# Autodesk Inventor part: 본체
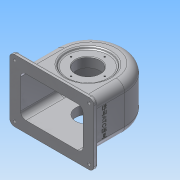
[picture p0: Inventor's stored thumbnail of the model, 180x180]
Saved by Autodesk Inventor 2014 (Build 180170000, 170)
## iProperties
Created: 2016-01
Part Number: 본체
Material: 알루미늄 6061
Document SubType Name: Modeling
Designer: user
Density: 2.71 g/cm^3
Appearance: 알루미늄 - 평지
Mass: 757.291 g
Surface Area: 1005.83 cm^2
Volume: 279.443 cm^3
Author: user
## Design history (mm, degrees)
sketch "스케치3"
  geometry: L1 (-57, -64)-(-57, 0); L2 (57, 0)-(57, -64); L3 (-57, -64)-(57, -64); A1 r 57 centre (0, 0) between (57, 0) and (-57, 0); 2 further points
  constraints: 6 end point, 3 point on circle, 2 tangent, 1 centre point, 1 coincident, 1 horizontal alignment, 1 parallel, 1 perpendicular, 1 vertical
  dimensions: "d6" = 64 distance of L1.start L1.end; "d7" = 121 vertical distance of L2.end point (0, 57)
extrude "돌출2" new body sketch "스케치3" distance "d8" = 77; taper "d9" = 0 deg
feature "쉘1" dims "d10" = 5
fillet "모깎기1" dims "d11" = 9
fillet "모깎기2" dims "d12" = 14
sketch "스케치4"
  geometry: L1 (100, 14)-(100, 63) reference; L2 (0, 77)-(86, 77) reference; L3 (-14, 14)-(-14, 63) reference; L4 (86, 0)-(0, 0) reference; L5 (-27, 90.5)-(113, 90.5); L6 (113, 90.5)-(113, -13.5); L7 (113, -13.5)-(-27, -13.5); L8 (-27, -13.5)-(-27, 90.5); A1 r 14 centre (86, 14) between (86, 0) and (100, 14) reference; A2 r 14 centre (86, 63) between (100, 63) and (86, 77) reference; A3 r 14 centre (0, 63) between (0, 77) and (-14, 63) reference; A4 r 14 centre (0, 14) between (-14, 14) and (0, 0) reference; 5 further points
  constraints: 8 end point, 4 midpoint, 2 parallel, 1 horizontal, 1 horizontal alignment, 1 perpendicular, 1 vertical alignment
  dimensions: "d13" = 104 distance of L7.end L5.start; "d14" = 140 distance of L5.start L5.end
extrude "돌출3" join sketch "스케치4" distance "d15" = 7; taper "d16" = 0 deg
sketch "스케치5"
  geometry: L1 (0, 63)-(0, 77) reference; L2 (0, 77)-(0, 77) reference; L3 (0, 63)-(0, 77) reference; L4 (0, 63)-(0, 63) reference; L5 (-57, 77)-(0, 77) reference; L6 (43, 72)-(0, 72) reference; L7 (35.747, 72)-(24, 58); L8 (24, 58)-(-4, 58); L9 (-4, 58)-(-4, 77); L10 (-64, -13.5)-(-64, 90.5) reference; L11 (0, 77)-(43, 77) reference; L12 (35.747, 72)-(-4, 72); 1 further point
  constraints: 8 end point, 2 parallel, 2 point on line, 1 horizontal alignment, 1 vertical
  dimensions: "d17" = 60 distance from line of L10 L9.end; "d18" = 50 deg angle of L8 L7; "d19" = 56 diameter of L7.end L9; "d20" = 19 distance between parallel lines of L8 L11
revolve "회전1" sketch "스케치5" stored, may be unused: angle "d21" = 90 deg
sketch "스케치6"
  geometry: L1 (0, 0)-(-57, 0) reference; L2 (-32, 58)-(24, 58) reference; L3 (43, 0)-(0, 0) reference; L4 (-4, -10)-(-4, 5); L5 (-64, -13.5)-(-64, 90.5) reference; L6 (-64, 5)-(0, 5) reference; L7 (-4, -10)-(27, -10); L8 (27, -10)-(27, 5); L9 (27, 5)-(-4, 5); 1 further point
  constraints: 8 end point, 2 parallel, 2 perpendicular, 1 horizontal alignment, 1 midpoint
  dimensions: "d69" = 60 distance between parallel lines of L5 L4; "d70" = 10 vertical distance of L3.start L4.start; "d71" = 62 diameter of L7.end L4
node "작업 평면2"
  node "작업 평면1"
sketch "스케치7"
  geometry: L1 (43, 0)-(-43, 0) reference; L2 (-57, 14)-(-57, 63) reference; C1 r 6 at (0, 38.5); 2 further points
  constraints: 1 centre point, 1 horizontal alignment, 1 midpoint, 1 vertical alignment
  dimensions: "d29" = 12 diameter of C1
extrude "돌출4" join sketch "스케치7" stored distance "d30" = 7; taper "d31" = 0 deg
fillet "모깎기3" dims "d32" = 3
hole "구멍1" diameter "d35" = 4.459; stored, may be unused: countersink angle "d39" = 90 deg, drill point angle "d41" = 0 deg; dims "d33" = 10, "d34" = 10, "d36" = 20, "d37" = 4, "d38" = 2, "d40" = 8
fillet "모깎기5" dims "d43" = 1
fillet "모깎기6" dims "d44" = 8
fillet "모깎기7" dims "d45" = 3
sketch "스케치9"
  geometry: C1 r 2.5 at (-19, -82.5); A1 r 5 centre (-19, -82.5) between (-24, -82.5) and (-19, -87.5) reference; 1 further point
  constraints: 1 centre point, 1 coincident
  dimensions: "d59" = 5 diameter of C1
extrude "돌출5" cut sketch "스케치9" stored distance "d60" = 7; taper "d61" = 0 deg
sketch "스케치10"
  geometry: C1 r 2.5 at (-19, 5.5); C2 r 2.5 at (105, 5.5); C3 r 2.5 at (105, -82.5); A1 r 5 centre (105, -82.5) between (105, -87.5) and (110, -82.5) reference; A2 r 5 centre (105, 5.5) between (110, 5.5) and (105, 10.5) reference; A3 r 5 centre (-19, 5.5) between (-19, 10.5) and (-24, 5.5) reference; 1 further point
  constraints: 3 centre point, 3 coincident, 2 equal radius
  dimensions: "d62" = 5 diameter of C1
extrude "돌출6" cut sketch "스케치10" stored distance "d63" = 7; taper "d64" = 0 deg
revolve "회전4" stored, may be unused: angle "d72" = 90 deg
hole "구멍3" diameter "d75" = 40; stored, may be unused: countersink angle "d79" = 90 deg, drill point angle "d81" = 0 deg; dims "d73" = 10, "d74" = 10, "d76" = 40, "d77" = 4, "d78" = 2, "d80" = 17
chamfer "모따기2" distance "d92" = 1; stored, may be unused: second distance "d93" = 2, angle "d94" = 45 deg
fillet "모깎기11" dims "d95" = 3
node "작업 평면3"
sketch "스케치12"
  geometry: C1 r 31 at (0, 0) reference; 2 further points
  constraints: 1 vertical alignment
  dimensions: "d107" = 24 distance of C1.centre point (0, 24)
hole "구멍6" sketch "스케치12" at (0, 24) diameter "d108" = 2.459; stored, may be unused: countersink angle "d112" = 90 deg, drill point angle "d114" = 118 deg; dims "d109" = 6, "d110" = 4, "d111" = 2, "d113" = 8
sketch "스케치13"
  geometry: L1 (-14, 0)-(-14, -56) reference; L2 (-19.5, -64)-(-27.5, -64) reference; 2 further points
  constraints: 1 other
  dimensions: "d118" = 38.5 distance from line of point (24.5, -34) L1; "d119" = 30 distance from line of point (24.5, -34) L2
feature "엠보싱1" sketch "스케치13" dims "d120" = 0.5, "d121" = 0
sketch "스케치14"
  geometry: L1 (-32, 58)-(24, 58) reference; L2 (35.747, 72)-(24, 58) reference; L3 (-4, 58)-(-4, 77); L4 (-64, 80)-(-64, 85) reference; L5 (0, 77)-(43, 77) reference; L6 (-4, 77)-(33.416, 77); L7 (33.416, 77)-(30.899, 74); L8 (30.899, 74)-(-4, 74); 1 further point
  constraints: 8 end point, 2 horizontal alignment, 2 perpendicular, 2 point on line, 1 parallel
  dimensions: "d122" = 60 distance between parallel lines of L4 L3; "d124" = 3 distance between parallel lines of L6 L8; "d125" = 5 distance between parallel lines of L2 L7
revolve "회전5" sketch "스케치14" stored, may be unused: angle "d126" = 90 deg
hole "구멍7" diameter "d129" = 40; stored, may be unused: countersink angle "d133" = 90 deg, drill point angle "d135" = 0 deg; dims "d127" = 10, "d128" = 10, "d130" = 6, "d131" = 4, "d132" = 2, "d134" = 20
sketch "스케치15"
  geometry: C1 r 20 at (0, 0) reference; 2 further points
  constraints: 1 vertical alignment
  dimensions: "d136" = 28 distance of C1.centre point (0, 28)
hole "구멍8" sketch "스케치15" at (0, 28) diameter "d137" = 2.459; stored, may be unused: countersink angle "d141" = 90 deg, drill point angle "d143" = 118 deg; dims "d138" = 7, "d139" = 4, "d140" = 2, "d142" = 9
chamfer "모따기3" distance "d147" = 1; stored, may be unused: second distance "d148" = 2, angle "d149" = 45 deg
fillet "모깎기12" dims "d150" = 3
fillet "모깎기13" dims "d151" = 3
node "솔리드2"
pattern_circular "원형 패턴2" dims angle "d116" = 360 deg
pattern_circular "원형 패턴3" dims angle "d145" = 360 deg
node "투영된 루프1"
other parameters: "d27" = 6
